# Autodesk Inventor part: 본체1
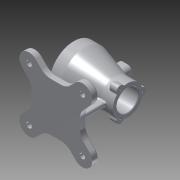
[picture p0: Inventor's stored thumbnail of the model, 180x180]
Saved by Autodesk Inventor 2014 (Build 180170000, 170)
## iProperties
Created: 2018-03
Part Number: 본체1
Material: 알루미늄 6061
Document SubType Name: Modeling
Designer: kb542
Density: 2.71 g/cm^3
Appearance: 알루미늄 - 평지
Author: kb542
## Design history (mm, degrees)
sketch "스케치1"
  geometry: L1 (0, 0)-(100, 0); L2 (0, 35)-(0, 45); L3 (0, 45)-(20, 45); L4 (20, 45)-(77, 27.5); L5 (77, 27.5)-(100, 27.5); L6 (100, 27.5)-(100, 20); L7 (100, 20)-(73, 20); L8 (70, 23)-(70, 23); L9 (67, 26)-(26, 26); L10 (23, 29)-(23, 32); L11 (20, 35)-(0, 35); A1 r 3 centre (20, 32) between (23, 32) and (20, 35); A2 r 3 centre (26, 29) between (23, 29) and (26, 26); A3 r 3 centre (67, 23) between (70, 23) and (67, 26); A4 r 3 centre (73, 23) between (70, 23) and (73, 20); 4 further points
  constraints: 22 end point, 8 point on circle, 8 point on line, 8 tangent, 5 parallel, 4 centre point, 4 perpendicular, 3 equal radius, 2 vertical alignment, 1 horizontal
  dimensions: "d0" = 100 distance of L1.start L1.end; "d1" = 20 distance of L2.end L3.end; "d2" = 77 horizontal distance of L4.end L2.end; "d3" = 23 distance of point (23, 35) L2.start; "d4" = 30 distance of L6.end point (70, 20); "d5" = 47 distance of point (70, 26) point (23, 26) (derived); "d6" = 90 diameter of L3 L1; "d7" = 40 diameter of L7 L1; "d8" = 52 diameter of L9 L1; "d9" = 70 diameter of L11 L1; "d10" = 55 diameter of L5 L1; "d11" = 3 radius of A1
revolve "회전1" sketch "스케치1" stored, may be unused: angle "d12" = 90 deg
sketch "스케치2"
  geometry: C1 r 20 at (0, 0) reference; C2 r 7 at (0, 27.5); 2 further points
  constraints: 3 vertical alignment, 1 centre point, 1 coincident, 3 other
  dimensions: "d13" = 14 diameter of C2
extrude "돌출1" join sketch "스케치2" distance "d14" = 15; taper "d15" = 0 deg
hole "구멍1" diameter "d21" = 3.242; stored, may be unused: countersink angle "d25" = 90 deg, drill point angle "d27" = 118 deg; dims "d19" = 10, "d20" = 10, "d22" = 9, "d23" = 4, "d24" = 2, "d26" = 11
node "작업 평면1"
sketch "스케치3"
  geometry: L1 (-93.5, 45)-(-3.5, 45); L2 (-3.5, 45)-(-3.5, -45); L3 (-3.5, -45)-(-93.5, -45); L4 (-93.5, -45)-(-93.5, 45); L5 (-20, 45)-(-77, 27.5) reference; 5 further points
  constraints: 8 end point, 3 midpoint, 2 parallel, 2 vertical alignment, 1 horizontal, 1 horizontal alignment, 1 perpendicular
  dimensions: "d32" = 90 distance of L3.end L1.start; "d33" = 90 distance of L1.start L1.end
extrude "돌출2" join sketch "스케치3" distance "d34" = 12; taper "d35" = 0 deg
sketch "스케치4"
  geometry: L1 (93.5, -45)-(93.5, 45) reference; L2 (93.5, 45)-(3.5, 45) reference; L3 (3.5, 45)-(3.5, -45) reference; L4 (48.5, 0)-(-0.997, 49.497); L5 (-21.5, 0)-(48.5, 0); L6 (11.73, 62.225)-(28.956, 45); L7 (-13.725, 36.77)-(3.5, 19.544); L8 (48.5, 45)-(48.5, 0); L9 (110.725, 36.77)-(93.5, 19.544); L10 (83.739, 60.483)-(68.255, 45); A1 r 70 centre (48.5, 0) between (-0.997, 49.497) and (-21.5, 0); A2 r 18 centre (-0.997, 49.497) between (11.73, 62.225) and (-13.725, 36.77); A3 r 18 centre (97.997, 49.497) between (110.725, 36.77) and (83.739, 60.483); 2 further points
  constraints: 14 end point, 7 point on circle, 4 point on line, 3 centre point, 3 parallel, 3 perpendicular, 3 tangent, 2 midpoint, 1 coincident, 1 horizontal alignment, 1 symmetric about line, 1 vertical alignment, 1 other
  dimensions: "d36" = 140 diameter of A1; "d37" = 45 deg angle of L4 L5; "d38" = 36 diameter of A2
extrude "돌출3" join sketch "스케치4" distance "d39" = 12; taper "d40" = 0 deg
node "작업 평면2"
node "작업 평면3"
sketch "스케치5"
  geometry: L1 (-45, -82)-(-45, -70) reference; L2 (-45, -70)-(45, -70) reference; L3 (45, -70)-(45, -82) reference; L4 (45, -82)-(-45, -82) reference; L5 (0, 0)-(0, -70); L6 (-19.391, -17.32)-(-24, -70); L7 (19.391, -17.32)-(24, -70); C1 r 35.789 at (0, 0) reference; A1 r 26 centre (0, 0) between (-19.391, -17.32) and (19.391, -17.32) reference; A2 r 26 centre (0, 0) between (-19.391, -17.32) and (19.391, -17.32); 1 further point
  constraints: 6 end point, 4 point on circle, 2 point on line, 1 centre point, 1 concentric, 1 midpoint, 1 other
  dimensions: "d41" = 24 distance from line of L6.end L5; "d42" = 95 deg angle of L6 L2
extrude "돌출4" join sketch "스케치5" stored distance "d43" = 8; taper "d44" = 0 deg
sketch "스케치6"
  geometry: L1 (48.255, 37)-(-8.745, 54.5) reference; L2 (48.255, 127)-(68.255, 127) reference; L3 (68.255, 127)-(68.255, 117) reference; L4 (68.255, 117)-(48.255, 117) reference; L5 (45.255, 114)-(45.255, 111) reference; L6 (42.255, 108)-(1.255, 108) reference; L7 (-4.745, 102)-(-31.745, 102) reference; L8 (-31.745, 102)-(-31.745, 107.879) reference; L9 (-31.745, 107.879)-(-20.745, 107.879) reference; L10 (-20.745, 107.879)-(-19.771, 109.5) reference; L11 (-19.771, 109.5)-(-20.745, 111.121) reference; L12 (-20.745, 111.121)-(-31.745, 111.121) reference; L13 (-31.745, 111.121)-(-31.745, 116.5) reference; L14 (-31.745, 116.5)-(-16.745, 116.5) reference; L15 (-16.745, 116.5)-(-16.745, 109.5) reference; L16 (-16.745, 109.5)-(-8.745, 109.5) reference; L17 (-8.745, 109.5)-(48.255, 127) reference; L18 (68.255, 37)-(48.255, 37) reference; L19 (48.255, 37)-(22.255, 44.982) reference; L20 (22.255, 44.982)-(22.255, 12) reference; L21 (22.255, 12)-(64.755, 12) reference; L22 (64.755, 12)-(64.755, 0) reference; L23 (64.755, 0)-(-25.245, 0) reference; L24 (-25.245, 0)-(-25.245, 12) reference; L25 (-25.245, 12)-(14.255, 12) reference; L26 (14.255, 12)-(14.255, 47.439) reference; L27 (14.255, 47.439)-(-8.745, 54.5) reference; L28 (-8.745, 54.5)-(-31.745, 54.5) reference; L29 (-31.745, 54.5)-(-31.745, 62) reference; L30 (-31.745, 62)-(-4.745, 62) reference; L31 (1.255, 56)-(42.255, 56) reference; L32 (45.255, 53)-(45.255, 50) reference; L33 (48.255, 47)-(68.255, 47) reference; L34 (68.255, 47)-(68.255, 37) reference; L35 (-18.745, 44.982)-(-18.745, 15.773); L36 (55.255, 35.008)-(55.255, 19.155); A1 r 3 centre (48.255, 114) between (48.255, 117) and (45.255, 114) reference; A2 r 3 centre (42.255, 111) between (42.255, 108) and (45.255, 111) reference; A3 r 3 centre (1.255, 105) between (1.255, 108) and (-1.745, 105) reference; A4 r 3 centre (-4.745, 105) between (-4.745, 102) and (-1.745, 105) reference; A5 r 3 centre (-4.745, 59) between (-1.745, 59) and (-4.745, 62) reference; A6 r 3 centre (1.255, 59) between (-1.745, 59) and (1.255, 56) reference; A7 r 3 centre (42.255, 53) between (45.255, 53) and (42.255, 56) reference; A8 r 3 centre (48.255, 50) between (45.255, 50) and (48.255, 47) reference; 1 further point
  constraints: 4 end point, 1 parallel
  dimensions: "d103" = 13 distance between parallel lines of L29 L35; "d104" = 13 distance between parallel lines of L34 L36
  node "절단 모서리 투영2"
feature "리브1" dims "d47" = 1, "d48" = 8, "d49" = 0, "d50" = 0, "d51" = 1, "d52" = 1
feature "리브2" dims "d53" = 1, "d54" = 8, "d55" = 0, "d56" = 0, "d57" = 1, "d58" = 1
sketch "스케치7" dims "d59" = 80
  geometry: C1 r 45 at (0, 0) reference; C2 r 35 at (0, 0) reference; 2 further points
  constraints: 2 vertical alignment, 1 coincident, 2 other
hole "구멍2" sketch "스케치7" at (0, 40) diameter "d60" = 3.242; stored, may be unused: countersink angle "d64" = 90 deg, drill point angle "d66" = 118 deg; dims "d61" = 9, "d62" = 4, "d63" = 2, "d65" = 11
node "작업 평면4"
sketch "스케치9"
  geometry: L1 (-54.5, 12.5)-(-45.5, 12.5); L2 (-37.5, 4.5)-(-37.5, -4.5); L3 (-45.5, -12.5)-(-54.5, -12.5); L4 (-62.5, -4.5)-(-62.5, 4.5); L5 (-77, -4)-(-54, -4) reference; L6 (-54, -4)-(-54, -20.322) reference; L7 (-46, -20.568)-(-46, -4) reference; L8 (-46, -4)-(-20, -4) reference; L9 (-20, -4)-(-20, 4) reference; L10 (-20, 4)-(-46, 4) reference; L11 (-46, 4)-(-46, 20.568) reference; L12 (-54, 20.322)-(-54, 4) reference; L13 (-54, 4)-(-77, 4) reference; L14 (-77, -4)-(-77, 4) reference; L15 (-28.956, 45)-(-68.255, 45) reference; L16 (0, 45)-(0, -45) reference; A1 r 8 centre (-54.5, 4.5) between (-54.5, 12.5) and (-62.5, 4.5); A2 r 8 centre (-45.5, 4.5) between (-37.5, 4.5) and (-45.5, 12.5); A3 r 8 centre (-45.5, -4.5) between (-45.5, -12.5) and (-37.5, -4.5); A4 r 8 centre (-54.5, -4.5) between (-62.5, -4.5) and (-54.5, -12.5); 7 further points
  constraints: 8 end point, 8 point on circle, 8 tangent, 6 point on line, 4 centre point, 3 equal radius, 3 midpoint, 2 parallel, 1 horizontal, 1 horizontal alignment, 1 perpendicular, 2 other
  dimensions: "d71" = 25 distance of point (-62.5, 12.5) point (-37.5, 12.5); "d72" = 25 distance of point (-62.5, -12.5) point (-62.5, 12.5); "d73" = 37.5 distance between parallel lines of L16 L2; "d74" = 8 radius of A1
extrude "돌출5" join sketch "스케치9" stored distance "d75" = 0; taper "d76" = 0 deg
sketch "스케치10"
  geometry: L1 (45.5, 12.5)-(54.5, 12.5) reference; L2 (45.5, 7.5)-(54.5, 7.5); L3 (57.5, 4.5)-(57.5, -4.5); L4 (54.5, -7.5)-(45.5, -7.5); L5 (42.5, -4.5)-(42.5, 4.5); A1 r 3 centre (45.5, 4.5) between (45.5, 7.5) and (42.5, 4.5); A2 r 3 centre (54.5, 4.5) between (57.5, 4.5) and (54.5, 7.5); A3 r 3 centre (54.5, -4.5) between (54.5, -7.5) and (57.5, -4.5); A4 r 3 centre (45.5, -4.5) between (42.5, -4.5) and (45.5, -7.5); 7 further points
  constraints: 8 end point, 8 point on circle, 8 tangent, 6 point on line, 4 centre point, 3 equal radius, 3 midpoint, 2 parallel, 1 horizontal, 1 horizontal alignment, 1 perpendicular, 1 vertical alignment
  dimensions: "d77" = 15 distance of point (42.5, 7.5) point (57.5, 7.5); "d78" = 15 distance of point (42.5, -7.5) point (42.5, 7.5); "d79" = 3 radius of A1
extrude "돌출6" cut sketch "스케치10" distance "d80" = 30; taper "d81" = 0 deg
fillet "모깎기1" dims "d82" = 3, "d83" = 1
fillet "모깎기2" dims "d84" = 3
fillet "모깎기3" dims "d85" = 1
fillet "모깎기4" dims "d89" = 3
fillet "모깎기5" dims "d90" = 3
chamfer "모따기1" distance "d91" = 1; stored, may be unused: second distance "d92" = 2, angle "d93" = 45 deg
sketch "스케치11"
  geometry: C1 r 5 at (-0.997, 49.497); C2 r 5 at (97.997, 49.497); C3 r 5 at (97.997, -49.497); C4 r 5 at (-0.997, -49.497); A1 r 18 centre (-0.997, -49.497) between (-13.725, -36.77) and (11.73, -62.225) reference; A2 r 18 centre (97.997, -49.497) between (83.739, -60.483) and (110.725, -36.77) reference; A3 r 18 centre (97.997, 49.497) between (110.725, 36.77) and (83.739, 60.483) reference; A4 r 18 centre (-0.997, 49.497) between (11.73, 62.225) and (-13.725, 36.77) reference; 1 further point
  constraints: 4 centre point, 4 coincident, 3 equal radius
  dimensions: "d94" = 10 diameter of C1
extrude "돌출7" cut sketch "스케치11" distance "d95" = 30; taper "d96" = 0 deg
fillet "모깎기6" dims "d97" = 25
fillet "모깎기7" dims "d98" = 3
sketch "스케치12"
  geometry: L1 (10, 1)-(10, -1) reference; L2 (39.311, 42)-(57.9, 42) reference; L3 (57.9, -42)-(39.311, -42) reference; L4 (90.5, 9.189)-(90.5, -9.189) reference; L5 (10, 0)-(90.5, 0); L6 (48.606, 42)-(48.606, -42); L7 (3.5, 9.189)-(3.5, -9.189) reference; 2 further points
  constraints: 4 end point, 4 midpoint, 1 other
  dimensions: "d99" = 35 distance from line of L5 point (48.5, -35); "d100" = 45 distance from line of L7 point (48.5, -35)
feature "엠보싱1" sketch "스케치12" dims "d0" = 100, "d101" = 0.5, "d102" = 0
sketch "스케치13"
  geometry: L1 (77.699, 50.201)-(86.003, 58.505) reference; L2 (39.311, 42)-(57.9, 42) reference; L3 (9.609, 60.104)-(19.512, 50.201) reference; L4 (-1.701, 28.988)-(-11.604, 38.891) reference; L5 (6.5, -9.189)-(6.5, 9.189) reference; L6 (-11.604, -38.891)-(-1.701, -28.988) reference; L7 (19.512, -50.201)-(9.609, -60.104) reference; L8 (57.9, -42)-(39.311, -42) reference; L9 (86.003, -58.505)-(77.699, -50.201) reference; L10 (98.701, -28.988)-(108.604, -38.891) reference; L11 (90.5, 9.189)-(90.5, -9.189) reference; L12 (108.604, 38.891)-(98.701, 28.988) reference; L13 (84, 7)-(57, 7) reference; L14 (90, -1)-(90, 1) reference; L15 (57, -7)-(84, -7) reference; L16 (57, -20.726)-(57, -7) reference; L17 (49, -26.749)-(51, -26.749) reference; L18 (43, -7)-(43, -20.726) reference; L19 (16, -7)-(43, -7) reference; L20 (10, 1)-(10, -1) reference; L21 (43, 7)-(16, 7) reference; L22 (43, 20.726)-(43, 7) reference; L23 (51, 26.749)-(49, 26.749) reference; L24 (57, 7)-(57, 20.726) reference; L25 (60.511, -34.824)-(60.511, -35.871) reference; L26 (62.899, -35.708)-(62.937, -36.007) reference; L27 (60.153, -36.191)-(60.153, -33.288) reference; L28 (60.153, -33.288)-(62.47, -33.288) reference; L29 (62.47, -33.288)-(62.47, -33.586) reference; L30 (62.47, -33.586)-(60.511, -33.586) reference; L31 (60.511, -33.586)-(60.511, -34.525) reference; L32 (60.511, -34.525)-(62.258, -34.525) reference; L33 (62.258, -34.525)-(62.258, -34.824) reference; L34 (62.258, -34.824)-(60.511, -34.824) reference; L35 (58.459, -32.832)-(58.459, -36.332) reference; L36 (58.459, -36.332)-(58.096, -36.332) reference; L37 (58.096, -36.332)-(58.096, -32.664) reference; L38 (58.096, -32.664)-(58.383, -32.664) reference; L39 (57.531, -32.913)-(57.531, -36.132) reference; L40 (57.531, -36.132)-(57.168, -36.132) reference; L41 (57.168, -36.132)-(57.168, -34.194) reference; L42 (57.168, -34.194)-(56.343, -34.194) reference; L43 (56.343, -34.194)-(56.343, -33.917) reference; L44 (56.343, -33.917)-(57.168, -33.917) reference; L45 (57.168, -33.917)-(57.168, -32.723) reference; L46 (57.168, -32.723)-(57.466, -32.723) reference; L47 (58.573, -37.103)-(58.573, -37.402) reference; L48 (58.573, -37.402)-(55.116, -37.402) reference; L49 (55.116, -37.402)-(55.116, -35.871) reference; L50 (55.116, -35.871)-(55.382, -35.871) reference; L51 (55.474, -36.034)-(55.474, -37.103) reference; L52 (55.474, -37.103)-(58.573, -37.103) reference; L53 (56.831, -35.198)-(56.587, -35.475) reference; L54 (54.432, -35.638)-(54.182, -35.366) reference; L55 (55.436, -32.875)-(55.756, -32.875) reference; L56 (53.325, -35.784)-(53.683, -35.784) reference; L57 (53.651, -34.259)-(53.287, -34.259) reference; L58 (49.721, -33.092)-(49.721, -33.423) reference; L59 (49.721, -33.423)-(48.473, -33.423) reference; L60 (48.473, -33.423)-(48.473, -37.092) reference; L61 (48.473, -37.092)-(48.109, -37.092) reference; L62 (48.109, -37.092)-(48.109, -33.423) reference; L63 (48.109, -33.423)-(46.866, -33.423) reference; L64 (46.866, -33.423)-(46.866, -33.092) reference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; C1 r 5 at (97.997, -49.497) reference; C2 r 5 at (-0.997, 49.497) reference; C3 r 5 at (97.997, 49.497) reference; C4 r 5 at (-0.997, -49.497) reference; A1 r 28 centre (57.9, 70) between (57.9, 42) and (77.699, 50.201) reference; A2 r 28 centre (39.311, 70) between (19.512, 50.201) and (39.311, 42) reference; A3 r 15 centre (-0.997, 49.497) between (9.609, 60.104) and (-11.604, 38.891) reference; A4 r 28 centre (-21.5, 9.189) between (6.5, 9.189) and (-1.701, 28.988) reference; A5 r 28 centre (-21.5, -9.189) between (-1.701, -28.988) and (6.5, -9.189) reference; A6 r 15 centre (-0.997, -49.497) between (-11.604, -38.891) and (9.609, -60.104) reference; A7 r 28 centre (39.311, -70) between (39.311, -42) and (19.512, -50.201) reference; A8 r 28 centre (57.9, -70) between (77.699, -50.201) and (57.9, -42) reference; A9 r 15 centre (97.997, -49.497) between (86.003, -58.505) and (108.604, -38.891) reference; A10 r 28 centre (118.5, -9.189) between (90.5, -9.189) and (98.701, -28.988) reference; A11 r 28 centre (118.5, 9.189) between (98.701, 28.988) and (90.5, 9.189) reference; A12 r 15 centre (97.997, 49.497) between (108.604, 38.891) and (86.003, 58.505) reference; A13 r 6 centre (84, 1) between (90, 1) and (84, 7) reference; A14 r 6 centre (84, -1) between (84, -7) and (90, -1) reference; A15 r 6 centre (16, -1) between (10, -1) and (16, -7) reference; A16 r 6 centre (16, 1) between (16, 7) and (10, 1) reference; 58 further points; 4 other entities
  constraints: 72 other
node "솔리드1"
pattern_circular "원형 패턴1" dims angle "d17" = 360 deg
pattern_circular "원형 패턴2" dims angle "d29" = 360 deg
mirror "대칭1"
pattern_circular "원형 패턴3" dims angle "d68" = 360 deg
pattern_circular "원형 패턴4" dims angle "d87" = 360 deg
node "투영된 루프1"
node "절단 모서리 투영1"
other parameters: "d31" = -82, "d70" = 45
